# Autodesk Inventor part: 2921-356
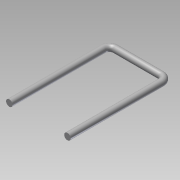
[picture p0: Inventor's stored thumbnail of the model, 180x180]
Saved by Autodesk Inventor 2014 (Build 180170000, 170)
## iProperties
Company: NHTSA/VRTC
Created: 2012-08
Part Number: 2921-356
Material: Steel, Mild
Document SubType Name: Modeling
Designer: Mike Vanvoorhis
Density: 7.86 g/cm^3
Mass: 61.8689 g
Surface Area: 50.2167 cm^2
Volume: 7.87136 cm^3
Project: CHILD SIDE IMPACT SLED
Description: LOWER ANCHOR, ANCHOR ROD
Stock Number: BAR Ø6.4 (Ø 1/4") x 266.0 (10 1/2")
Appearance: Steel
Author: Dave Walker
Title: Lower Anchor, Anchor Rod
Subject: Child Side Impact Sled
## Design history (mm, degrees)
sketch "Sketch1"
  geometry: C1 r 3.175 at (0, 0); C2 r 3.175 at (57.15, 0); 1 further point
  constraints: 2 centre point, 1 coincident
  dimensions: "d0" = 6.35 diameter of C1; "d3" = 6.35 diameter of C2
node "3D Sketch1"
sketch "3D Sketch2"
  geometry: L1 through (0, -92.075) direction (0, -1); L2 through (0, -92.075) direction (0, -1); 6 other entities
  constraints: 4 vertical
  dimensions: "d1" = 6.35 dimension on L1; "d2" = 6.35 dimension on L2 (= d1)
sweep "Sweep1" sketch "3D Sketch2" dims "d5" = 0
body "Solid1"
